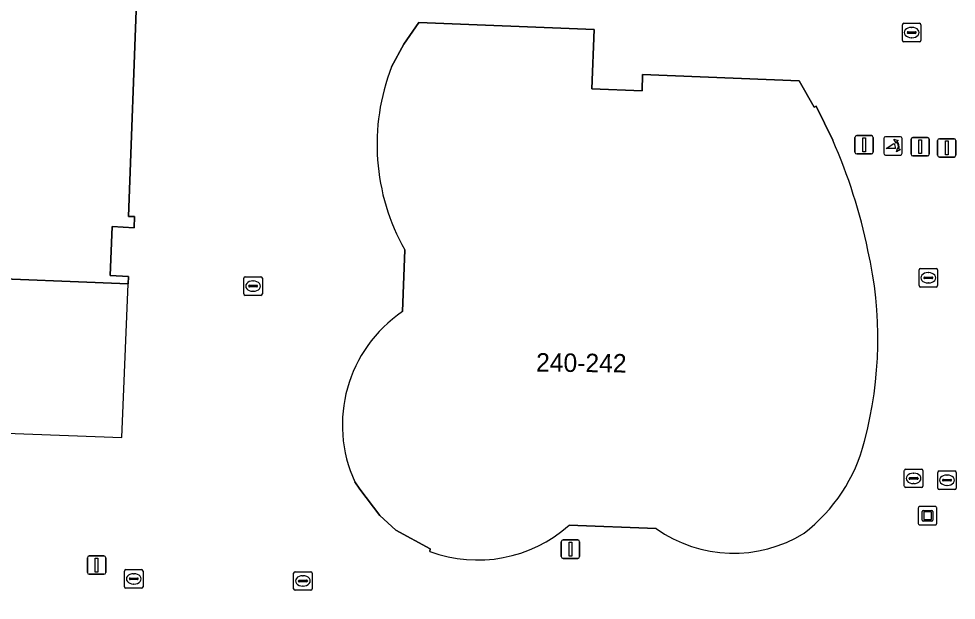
# Model space of a CAD drawing. Extents: x 160888 to 161385, y 386490 to 386908.
# Drawn here: x 161089.9 to 161140.7, y 386517.3 to 386548.8 of the extents above; entities that cross this region are included whole.
import ezdxf

# ---------------------------------------------------------------- set-up
doc = ezdxf.new("R2010")
doc.units = 0
for name, color, linetype in [('IMGEO_Afsluitpaal', 7, 'Continuous'), ('IMGEO_Kolk', 7, 'Continuous'), ('IMGEO_Kunstobject', 7, 'Continuous'), ('IMGEO_Lichtmast', 7, 'Continuous'), ('IMGEO_Pand', 7, 'Continuous'), ('IMGEO_Pand_nummerreeks', 7, 'Continuous'), ('IMGEO_Pand_overbouw', 7, 'Continuous'), ('IMGEO_Poller', 7, 'Continuous'), ('IMGEO_Rioolput', 7, 'Continuous'), ('IMGEO_Voetgangersgebied_open', 7, 'Continuous')]:
    doc.layers.add(name, color=color, linetype=linetype)

msp = doc.modelspace()

# ---------------------------------------------------------------- linework, layer by layer
at = {"layer": 'IMGEO_Afsluitpaal'}
for p, q in [((161135.291, 386542.505), (161136.081, 386542.505)), ((161136.081, 386542.505), (161135.291, 386542.505)), ((161135.191, 386541.605), (161135.191, 386542.405)), ((161135.191, 386542.405), (161135.191, 386541.605)), ((161136.181, 386542.405), (161136.181, 386541.605)), ((161136.181, 386541.605), (161136.181, 386542.405)), ((161138.234, 386541.499), (161138.234, 386542.299)), ((161138.234, 386542.299), (161138.234, 386541.499)), ((161138.334, 386542.399), (161139.124, 386542.399)), ((161139.124, 386542.399), (161138.334, 386542.399)), ((161139.224, 386542.299), (161139.224, 386541.499)), ((161139.224, 386541.499), (161139.224, 386542.299)), ((161139.674, 386541.434), (161139.674, 386542.234)), ((161139.674, 386542.234), (161139.674, 386541.434)), ((161139.774, 386542.334), (161140.564, 386542.334)), ((161140.564, 386542.334), (161139.774, 386542.334)), ((161140.664, 386542.234), (161140.664, 386541.434)), ((161140.664, 386541.434), (161140.664, 386542.234)), ((161136.081, 386541.505), (161135.291, 386541.505)), ((161135.291, 386541.505), (161136.081, 386541.505)), ((161139.124, 386541.399), (161138.334, 386541.399)), ((161138.334, 386541.399), (161139.124, 386541.399)), ((161140.564, 386541.334), (161139.774, 386541.334)), ((161139.774, 386541.334), (161140.564, 386541.334))]:
    msp.add_line(p, q, dxfattribs=at)
for points in [[(161135.611, 386542.38), (161135.761, 386542.38), (161135.761, 386541.63), (161135.611, 386541.63), (161135.611, 386542.38)], [(161138.654, 386542.274), (161138.804, 386542.274), (161138.804, 386541.524), (161138.654, 386541.524), (161138.654, 386542.274)], [(161140.094, 386542.209), (161140.244, 386542.209), (161140.244, 386541.459), (161140.094, 386541.459), (161140.094, 386542.209)]]:
    msp.add_lwpolyline(points, dxfattribs=at)
for centre, start, end in [((161135.291, 386542.405), 90, 180), ((161135.291, 386542.405), 90, 180), ((161136.081, 386542.405), 0, 90), ((161136.081, 386542.405), 360, 90), ((161138.334, 386542.299), 90, 180), ((161138.334, 386542.299), 90, 180), ((161139.124, 386542.299), 0, 90), ((161139.124, 386542.299), 360, 90), ((161139.774, 386542.234), 90, 180), ((161139.774, 386542.234), 90, 180), ((161140.564, 386542.234), 0, 90), ((161140.564, 386542.234), 360, 90), ((161135.291, 386541.605), 180, 270), ((161135.291, 386541.605), 180, 270), ((161136.081, 386541.605), 270, 0), ((161136.081, 386541.605), 270, 0), ((161138.334, 386541.499), 180, 270), ((161138.334, 386541.499), 180, 270), ((161139.124, 386541.499), 270, 0), ((161139.124, 386541.499), 270, 0), ((161139.774, 386541.434), 180, 270), ((161139.774, 386541.434), 180, 270), ((161140.564, 386541.434), 270, 0), ((161140.564, 386541.434), 270, 0)]:
    msp.add_arc(centre, 0.1, start, end, dxfattribs=at)
at = {"layer": 'IMGEO_Kolk'}
for p, q in [((161102.133, 386534.838), (161102.985, 386534.838)), ((161138.668, 386534.363), (161138.668, 386535.215)), ((161138.743, 386535.289), (161139.595, 386535.289)), ((161139.156, 386535.069), (161139.181, 386535.069)), ((161139.669, 386535.215), (161139.669, 386534.363)), ((161102.058, 386533.912), (161102.058, 386534.764)), ((161102.317, 386534.332), (161102.317, 386534.344)), ((161102.36, 386534.381), (161102.758, 386534.381)), ((161102.546, 386534.618), (161102.571, 386534.618)), ((161102.801, 386534.344), (161102.801, 386534.332)), ((161103.059, 386534.764), (161103.059, 386533.912)), ((161138.927, 386534.783), (161138.927, 386534.795)), ((161139.365, 386534.746), (161138.967, 386534.746)), ((161138.97, 386534.832), (161139.368, 386534.832)), ((161139.179, 386534.509), (161139.154, 386534.509)), ((161139.411, 386534.795), (161139.411, 386534.783)), ((161102.985, 386533.838), (161102.133, 386533.838)), ((161102.755, 386534.295), (161102.357, 386534.295)), ((161102.569, 386534.058), (161102.544, 386534.058)), ((161139.595, 386534.289), (161138.743, 386534.289)), ((161139.683, 386523.387), (161139.683, 386524.239)), ((161139.758, 386524.313), (161140.61, 386524.313)), ((161140.684, 386524.239), (161140.684, 386523.387)), ((161139.942, 386523.807), (161139.942, 386523.819)), ((161140.38, 386523.77), (161139.982, 386523.77)), ((161139.985, 386523.856), (161140.383, 386523.856)), ((161140.171, 386524.093), (161140.196, 386524.093)), ((161140.426, 386523.819), (161140.426, 386523.807)), ((161140.61, 386523.313), (161139.758, 386523.313)), ((161140.194, 386523.533), (161140.169, 386523.533)), ((161095.587, 386518.036), (161095.587, 386518.888)), ((161095.662, 386518.962), (161096.514, 386518.962)), ((161096.075, 386518.742), (161096.1, 386518.742)), ((161096.588, 386518.888), (161096.588, 386518.036)), ((161104.756, 386517.922), (161104.756, 386518.774)), ((161104.831, 386518.848), (161105.683, 386518.848)), ((161105.244, 386518.628), (161105.269, 386518.628)), ((161105.757, 386518.774), (161105.757, 386517.922)), ((161095.846, 386518.456), (161095.846, 386518.468)), ((161096.284, 386518.419), (161095.886, 386518.419)), ((161095.889, 386518.505), (161096.287, 386518.505)), ((161096.098, 386518.182), (161096.073, 386518.182)), ((161096.33, 386518.468), (161096.33, 386518.456)), ((161105.015, 386518.342), (161105.015, 386518.354)), ((161105.453, 386518.305), (161105.055, 386518.305)), ((161105.058, 386518.391), (161105.456, 386518.391)), ((161105.267, 386518.068), (161105.242, 386518.068)), ((161105.499, 386518.354), (161105.499, 386518.342)), ((161096.514, 386517.962), (161095.662, 386517.962)), ((161105.683, 386517.848), (161104.831, 386517.848))]:
    msp.add_line(p, q, dxfattribs=at)
for points in [[(161102.133, 386534.838), (161102.985, 386534.838)], [(161138.668, 386534.363), (161138.668, 386535.215)], [(161138.743, 386535.289), (161139.595, 386535.289)], [(161139.669, 386535.215), (161139.669, 386534.363)], [(161102.058, 386533.912), (161102.058, 386534.764)], [(161103.059, 386534.764), (161103.059, 386533.912)], [(161102.985, 386533.838), (161102.133, 386533.838)], [(161139.595, 386534.289), (161138.743, 386534.289)], [(161139.683, 386523.387), (161139.683, 386524.239)], [(161139.758, 386524.313), (161140.61, 386524.313)], [(161140.684, 386524.239), (161140.684, 386523.387)], [(161140.61, 386523.313), (161139.758, 386523.313)], [(161095.587, 386518.036), (161095.587, 386518.888)], [(161095.662, 386518.962), (161096.514, 386518.962)], [(161096.588, 386518.888), (161096.588, 386518.036)], [(161104.756, 386517.922), (161104.756, 386518.774)], [(161104.831, 386518.848), (161105.683, 386518.848)], [(161105.757, 386518.774), (161105.757, 386517.922)], [(161096.514, 386517.962), (161095.662, 386517.962)], [(161105.683, 386517.848), (161104.831, 386517.848)]]:
    msp.add_lwpolyline(points, dxfattribs=at)
for centre, radius, start, end in [((161102.135, 386534.762), 0.0765, 91.552, 178.448), ((161102.135, 386534.762), 0.0765, 91.552, 178.448), ((161102.983, 386534.762), 0.0765, 1.552, 88.448), ((161102.983, 386534.762), 0.0765, 1.552, 88.448), ((161138.745, 386535.213), 0.0765, 91.552, 178.448), ((161138.745, 386535.213), 0.0765, 91.552, 178.448), ((161139.593, 386535.213), 0.0765, 1.552, 88.448), ((161139.593, 386535.213), 0.0765, 1.552, 88.448), ((161102.357, 386534.341), 0.0403, 85.8775, 175.7526), ((161102.354, 386534.331), 0.0366, 178.938, 274.7102), ((161102.758, 386534.338), 0.043, 264.8664, 352.4533), ((161102.762, 386534.343), 0.0386, 1.7309, 96.639), ((161138.745, 386534.365), 0.0765, 181.552, 268.448), ((161138.745, 386534.365), 0.0765, 181.552, 268.448), ((161138.967, 386534.792), 0.0403, 85.8775, 175.7526), ((161138.964, 386534.782), 0.0366, 178.938, 274.7102), ((161139.368, 386534.789), 0.043, 264.8664, 352.4533), ((161139.372, 386534.794), 0.0386, 1.7309, 96.639), ((161139.593, 386534.365), 0.0765, 271.552, 358.448), ((161139.593, 386534.365), 0.0765, 271.552, 358.448), ((161102.135, 386533.914), 0.0765, 181.552, 268.448), ((161102.135, 386533.914), 0.0765, 181.552, 268.448), ((161102.983, 386533.914), 0.0765, 271.552, 358.448), ((161102.983, 386533.914), 0.0765, 271.552, 358.448), ((161139.76, 386524.237), 0.0765, 91.552, 178.448), ((161139.76, 386524.237), 0.0765, 91.552, 178.448), ((161140.608, 386524.237), 0.0765, 1.552, 88.448), ((161140.608, 386524.237), 0.0765, 1.552, 88.448), ((161139.982, 386523.816), 0.0403, 85.8775, 175.7526), ((161139.979, 386523.806), 0.0366, 178.938, 274.7102), ((161140.383, 386523.813), 0.043, 264.8664, 352.4533), ((161140.387, 386523.818), 0.0386, 1.7309, 96.639), ((161139.76, 386523.389), 0.0765, 181.552, 268.448), ((161139.76, 386523.389), 0.0765, 181.552, 268.448), ((161140.608, 386523.389), 0.0765, 271.552, 358.448), ((161140.608, 386523.389), 0.0765, 271.552, 358.448), ((161095.664, 386518.886), 0.0765, 91.552, 178.448), ((161095.664, 386518.886), 0.0765, 91.552, 178.448), ((161096.512, 386518.886), 0.0765, 1.552, 88.448), ((161096.512, 386518.886), 0.0765, 1.552, 88.448), ((161104.833, 386518.772), 0.0765, 91.552, 178.448), ((161104.833, 386518.772), 0.0765, 91.552, 178.448), ((161105.681, 386518.772), 0.0765, 1.552, 88.448), ((161105.681, 386518.772), 0.0765, 1.552, 88.448), ((161095.886, 386518.465), 0.0403, 85.8775, 175.7526), ((161095.883, 386518.455), 0.0366, 178.938, 274.7102), ((161096.287, 386518.462), 0.043, 264.8664, 352.4533), ((161096.291, 386518.467), 0.0386, 1.7309, 96.639), ((161105.055, 386518.351), 0.0403, 85.8775, 175.7526), ((161105.052, 386518.341), 0.0366, 178.938, 274.7102), ((161105.456, 386518.348), 0.043, 264.8664, 352.4533), ((161105.46, 386518.353), 0.0386, 1.7309, 96.639), ((161095.664, 386518.038), 0.0765, 181.552, 268.448), ((161095.664, 386518.038), 0.0765, 181.552, 268.448), ((161096.512, 386518.038), 0.0765, 271.552, 358.448), ((161096.512, 386518.038), 0.0765, 271.552, 358.448), ((161104.833, 386517.924), 0.0765, 181.552, 268.448), ((161104.833, 386517.924), 0.0765, 181.552, 268.448), ((161105.681, 386517.924), 0.0765, 271.552, 358.448), ((161105.681, 386517.924), 0.0765, 271.552, 358.448)]:
    msp.add_arc(centre, radius, start, end, dxfattribs=at)
for centre, major_axis, ratio, start_param, end_param in [((161139.155, 386534.789), (-0.387, 0.002), 0.722429, 4.712389, 7.853982), ((161139.18, 386534.789), (-0.39, 0.002), 0.717154, 1.570796, 4.712389), ((161102.545, 386534.338), (-0.387, 0.002), 0.722429, 4.712389, 7.853982), ((161102.57, 386534.338), (-0.39, 0.002), 0.717154, 1.570796, 4.712389), ((161140.17, 386523.813), (-0.387, 0.002), 0.722429, 4.712389, 7.853982), ((161140.195, 386523.813), (-0.39, 0.002), 0.717154, 1.570796, 4.712389), ((161096.074, 386518.462), (-0.387, 0.002), 0.722429, 4.712389, 7.853982), ((161096.099, 386518.462), (-0.39, 0.002), 0.717154, 1.570796, 4.712389), ((161105.243, 386518.348), (-0.387, 0.002), 0.722429, 4.712389, 7.853982), ((161105.268, 386518.348), (-0.39, 0.002), 0.717154, 1.570796, 4.712389)]:
    msp.add_ellipse(centre, major_axis=major_axis, ratio=ratio, start_param=start_param, end_param=end_param, dxfattribs=at)
at = {"layer": 'IMGEO_Kunstobject'}
for p, q in [((161138.626, 386522.301), (161138.626, 386521.46)), ((161138.626, 386522.301), (161138.626, 386521.46)), ((161139.542, 386522.385), (161138.701, 386522.385)), ((161139.542, 386522.385), (161138.701, 386522.385)), ((161138.89, 386522.173), (161139.364, 386522.173)), ((161139.626, 386521.469), (161139.626, 386522.31)), ((161139.626, 386521.469), (161139.626, 386522.31)), ((161138.84, 386521.649), (161138.84, 386522.123)), ((161138.92, 386522.073), (161138.92, 386521.699)), ((161139.314, 386522.093), (161138.94, 386522.093)), ((161138.94, 386521.679), (161139.314, 386521.679)), ((161139.334, 386521.699), (161139.334, 386522.073)), ((161139.414, 386522.123), (161139.414, 386521.649)), ((161138.71, 386521.385), (161139.551, 386521.385)), ((161138.71, 386521.385), (161139.551, 386521.385)), ((161139.364, 386521.599), (161138.89, 386521.599))]:
    msp.add_line(p, q, dxfattribs=at)
for centre, radius, start, end in [((161138.704, 386522.307), 0.0779, 92.4484, 184.2845), ((161138.704, 386522.307), 0.0779, 92.4484, 184.2845), ((161138.89, 386522.123), 0.05, 90, 180), ((161139.364, 386522.123), 0.05, 360, 90), ((161139.548, 386522.307), 0.0779, 2.4484, 94.2845), ((161139.548, 386522.307), 0.0779, 2.4484, 94.2845), ((161138.89, 386521.649), 0.05, 180, 270), ((161138.94, 386522.073), 0.02, 90, 180), ((161138.94, 386521.699), 0.02, 180, 270), ((161139.314, 386522.073), 0.02, 360, 90), ((161139.314, 386521.699), 0.02, 270, 0), ((161139.364, 386521.649), 0.05, 270, 0), ((161138.704, 386521.463), 0.0779, 182.4484, 274.2845), ((161138.704, 386521.463), 0.0779, 182.4484, 274.2845), ((161139.548, 386521.463), 0.0779, 272.4484, 4.2845), ((161139.548, 386521.463), 0.0779, 272.4484, 4.2845)]:
    msp.add_arc(centre, radius, start, end, dxfattribs=at)
at = {"layer": 'IMGEO_Lichtmast'}
for p, q in [((161119.269, 386519.671), (161119.269, 386520.471)), ((161119.269, 386520.471), (161119.269, 386519.671)), ((161119.369, 386520.571), (161120.159, 386520.571)), ((161120.159, 386520.571), (161119.369, 386520.571)), ((161120.259, 386520.471), (161120.259, 386519.671)), ((161120.259, 386519.671), (161120.259, 386520.471)), ((161093.573, 386518.808), (161093.573, 386519.608)), ((161093.573, 386519.608), (161093.573, 386518.808)), ((161093.673, 386519.708), (161094.463, 386519.708)), ((161094.463, 386519.708), (161093.673, 386519.708)), ((161094.563, 386519.608), (161094.563, 386518.808)), ((161094.563, 386518.808), (161094.563, 386519.608)), ((161120.159, 386519.571), (161119.369, 386519.571)), ((161119.369, 386519.571), (161120.159, 386519.571)), ((161094.463, 386518.708), (161093.673, 386518.708)), ((161093.673, 386518.708), (161094.463, 386518.708))]:
    msp.add_line(p, q, dxfattribs=at)
for points in [[(161119.689, 386520.446), (161119.839, 386520.446), (161119.839, 386519.696), (161119.689, 386519.696), (161119.689, 386520.446)], [(161093.993, 386519.583), (161094.143, 386519.583), (161094.143, 386518.833), (161093.993, 386518.833), (161093.993, 386519.583)]]:
    msp.add_lwpolyline(points, dxfattribs=at)
for centre, start, end in [((161119.369, 386520.471), 90, 180), ((161119.369, 386520.471), 90, 180), ((161120.159, 386520.471), 0, 90), ((161120.159, 386520.471), 360, 90), ((161093.673, 386519.608), 90, 180), ((161093.673, 386519.608), 90, 180), ((161094.463, 386519.608), 0, 90), ((161094.463, 386519.608), 360, 90), ((161119.369, 386519.671), 180, 270), ((161119.369, 386519.671), 180, 270), ((161120.159, 386519.671), 270, 0), ((161120.159, 386519.671), 270, 0), ((161093.673, 386518.808), 180, 270), ((161093.673, 386518.808), 180, 270), ((161094.463, 386518.808), 270, 0), ((161094.463, 386518.808), 270, 0)]:
    msp.add_arc(centre, 0.1, start, end, dxfattribs=at)
at = {"layer": 'IMGEO_Pand'}
for points in [[(161002.953, 386513.11), (161051.083, 386511.057), (161051.206, 386511.052), (161052.017, 386528.899), (161080.022, 386527.764), (161080.132, 386529.382), (161081.504, 386529.308), (161086.537, 386529.035), (161086.775, 386534.825), (161095.779, 386534.461), (161095.797, 386534.862), (161094.798, 386534.906), (161094.918, 386537.567), (161096.112, 386537.502), (161096.134, 386538.109), (161095.807, 386538.111), (161096.256, 386550.282), (161074.659, 386551.192), (161041.832, 386552.576), (161041.925, 386554.908), (161042.136, 386560.18), (161042.986, 386581.802), (161011.368, 386583.058)], [(161133.984, 386542.246), (161133.082, 386544.09), (161132.989, 386544.045), (161132.172, 386545.476), (161123.673, 386545.824), (161123.652, 386544.924), (161120.928, 386545.042), (161121.056, 386548.259), (161111.552, 386548.634), (161110.736, 386547.454), (161110.068, 386546.223)], [(161110.787, 386536.307), (161110.654, 386532.956)], [(161108.077, 386523.72), (161108.346, 386523.332), (161109.425, 386521.897), (161110.299, 386521.096), (161112.164, 386520.096), (161112.145, 386519.949)], [(161119.688, 386521.369), (161124.412, 386521.191)]]:
    msp.add_lwpolyline(points, dxfattribs=at)
for centre, radius, start, end in [((161120.826, 386542.019), 11.551, 158.6561, 209.6383), ((161107.732, 386530.554), 28.738, 11.4916, 24.0075), ((161114.811, 386531.479), 21.623, 345.1161, 12.8256), ((161114.811, 386526.819), 7.412, 124.1093, 204.7107), ((161126.927, 386528.129), 9.053, 307.4647, 345.9122), ((161114.735, 386526.936), 7.451, 249.6615, 311.6613), ((161128.61, 386527.104), 7.252, 234.6294, 301.8291)]:
    msp.add_arc(centre, radius, start, end, dxfattribs=at)
at = {"layer": 'IMGEO_Pand_overbouw'}
msp.add_lwpolyline([(161080.022, 386527.764), (161079.988, 386526.704), (161081.426, 386526.65), (161095.446, 386526.126), (161095.779, 386534.461), (161086.775, 386534.825), (161086.537, 386529.035), (161081.504, 386529.308), (161080.132, 386529.382)], close=True, dxfattribs=at)
at = {"layer": 'IMGEO_Poller'}
for p, q in [((161136.755, 386542.347), (161136.755, 386541.54)), ((161136.755, 386542.347), (161136.755, 386541.54)), ((161137.657, 386542.442), (161136.849, 386542.442)), ((161137.657, 386542.442), (161136.849, 386542.442)), ((161137.751, 386541.54), (161137.751, 386542.347)), ((161137.751, 386541.54), (161137.751, 386542.347)), ((161136.849, 386541.445), (161137.657, 386541.445)), ((161136.849, 386541.445), (161137.657, 386541.445))]:
    msp.add_line(p, q, dxfattribs=at)
for points in [[(161137.39, 386541.798), (161136.877, 386541.798), (161137.307, 386542.073)], [(161137.434, 386542.171), (161137.422, 386542.098), (161137.297, 386542.303)], [(161137.297, 386542.303), (161137.528, 386542.237), (161137.457, 386542.205)], [(161137.45, 386541.626), (161137.516, 386541.857), (161137.546, 386541.789)], [(161137.582, 386541.762), (161137.654, 386541.751), (161137.45, 386541.626)]]:
    msp.add_lwpolyline(points, dxfattribs=at)
for centre, radius, start, end in [((161136.849, 386542.347), 0.0946, 90, 180), ((161136.849, 386542.347), 0.0946, 90, 180), ((161137.062, 386541.848), 0.332, 351.3247, 42.4854), ((161137.076, 386541.858), 0.476, 351.7527, 41.1691), ((161137.076, 386541.858), 0.516, 349.3569, 42.2912), ((161137.657, 386542.347), 0.0946, 0, 90), ((161137.657, 386542.347), 0.0946, 0, 90), ((161136.849, 386541.54), 0.0946, 180, 270), ((161136.849, 386541.54), 0.0946, 180, 270), ((161137.657, 386541.54), 0.0946, 270, 0), ((161137.657, 386541.54), 0.0946, 270, 0)]:
    msp.add_arc(centre, radius, start, end, dxfattribs=at)
at = {"layer": 'IMGEO_Rioolput'}
for p, q in [((161137.844, 386548.59), (161138.696, 386548.59)), ((161137.769, 386547.664), (161137.769, 386548.516)), ((161138.028, 386548.084), (161138.028, 386548.096)), ((161138.071, 386548.133), (161138.469, 386548.133)), ((161138.257, 386548.37), (161138.282, 386548.37)), ((161138.512, 386548.096), (161138.512, 386548.084)), ((161138.77, 386548.516), (161138.77, 386547.664)), ((161138.696, 386547.59), (161137.844, 386547.59)), ((161138.466, 386548.047), (161138.068, 386548.047)), ((161138.28, 386547.81), (161138.255, 386547.81)), ((161137.869, 386523.484), (161137.869, 386524.336)), ((161137.944, 386524.41), (161138.796, 386524.41)), ((161138.357, 386524.19), (161138.382, 386524.19)), ((161138.87, 386524.336), (161138.87, 386523.484)), ((161138.128, 386523.904), (161138.128, 386523.916)), ((161138.566, 386523.867), (161138.168, 386523.867)), ((161138.171, 386523.953), (161138.569, 386523.953)), ((161138.612, 386523.916), (161138.612, 386523.904)), ((161138.796, 386523.41), (161137.944, 386523.41)), ((161138.38, 386523.63), (161138.355, 386523.63))]:
    msp.add_line(p, q, dxfattribs=at)
for points in [[(161137.844, 386548.59), (161138.696, 386548.59)], [(161137.769, 386547.664), (161137.769, 386548.516)], [(161138.77, 386548.516), (161138.77, 386547.664)], [(161138.696, 386547.59), (161137.844, 386547.59)], [(161137.869, 386523.484), (161137.869, 386524.336)], [(161137.944, 386524.41), (161138.796, 386524.41)], [(161138.87, 386524.336), (161138.87, 386523.484)], [(161138.796, 386523.41), (161137.944, 386523.41)]]:
    msp.add_lwpolyline(points, dxfattribs=at)
for centre, radius, start, end in [((161137.846, 386548.514), 0.0765, 91.552, 178.448), ((161137.846, 386548.514), 0.0765, 91.552, 178.448), ((161138.694, 386548.514), 0.0765, 1.552, 88.448), ((161138.694, 386548.514), 0.0765, 1.552, 88.448), ((161138.068, 386548.093), 0.0403, 85.8775, 175.7526), ((161138.065, 386548.083), 0.0366, 178.938, 274.7102), ((161138.469, 386548.09), 0.043, 264.8664, 352.4533), ((161138.473, 386548.095), 0.0386, 1.7309, 96.639), ((161137.846, 386547.666), 0.0765, 181.552, 268.448), ((161137.846, 386547.666), 0.0765, 181.552, 268.448), ((161138.694, 386547.666), 0.0765, 271.552, 358.448), ((161138.694, 386547.666), 0.0765, 271.552, 358.448), ((161137.946, 386524.334), 0.0765, 91.552, 178.448), ((161137.946, 386524.334), 0.0765, 91.552, 178.448), ((161138.794, 386524.334), 0.0765, 1.552, 88.448), ((161138.794, 386524.334), 0.0765, 1.552, 88.448), ((161138.168, 386523.913), 0.0403, 85.8775, 175.7526), ((161138.165, 386523.903), 0.0366, 178.938, 274.7102), ((161138.569, 386523.91), 0.043, 264.8664, 352.4533), ((161138.573, 386523.915), 0.0386, 1.7309, 96.639), ((161137.946, 386523.486), 0.0765, 181.552, 268.448), ((161137.946, 386523.486), 0.0765, 181.552, 268.448), ((161138.794, 386523.486), 0.0765, 271.552, 358.448), ((161138.794, 386523.486), 0.0765, 271.552, 358.448)]:
    msp.add_arc(centre, radius, start, end, dxfattribs=at)
for centre, major_axis, ratio, start_param, end_param in [((161138.256, 386548.09), (-0.387, 0.002), 0.722429, 4.712389, 7.853982), ((161138.281, 386548.09), (-0.39, 0.002), 0.717154, 1.570796, 4.712389), ((161138.356, 386523.91), (-0.387, 0.002), 0.722429, 4.712389, 7.853982), ((161138.381, 386523.91), (-0.39, 0.002), 0.717154, 1.570796, 4.712389)]:
    msp.add_ellipse(centre, major_axis=major_axis, ratio=ratio, start_param=start_param, end_param=end_param, dxfattribs=at)
at = {"layer": 'IMGEO_Voetgangersgebied_open'}
for points in [[(161042.986, 386581.802), (161042.136, 386560.18), (161041.925, 386554.908), (161041.832, 386552.576), (161074.659, 386551.192), (161096.256, 386550.282), (161095.807, 386538.111), (161096.134, 386538.109), (161096.112, 386537.502), (161094.918, 386537.567), (161094.798, 386534.906), (161095.797, 386534.862), (161095.779, 386534.461), (161086.775, 386534.825), (161086.537, 386529.035), (161081.504, 386529.308), (161080.132, 386529.382), (161080.022, 386527.764), (161052.017, 386528.899), (161051.206, 386511.052), (161051.083, 386511.057), (161051.677, 386507.711), (161054.692, 386507.633), (161095.632, 386509.131)], [(161110.068, 386546.223), (161110.736, 386547.454), (161111.552, 386548.634), (161121.056, 386548.259), (161120.928, 386545.042), (161123.652, 386544.924), (161123.673, 386545.824), (161132.172, 386545.476), (161132.989, 386544.045), (161133.082, 386544.09), (161133.984, 386542.246)], [(161110.654, 386532.956), (161110.787, 386536.307)], [(161112.145, 386519.949), (161112.164, 386520.096), (161110.299, 386521.096), (161109.425, 386521.897), (161108.346, 386523.332), (161108.077, 386523.72)], [(161124.412, 386521.191), (161119.688, 386521.369)]]:
    msp.add_lwpolyline(points, dxfattribs=at)
for centre, radius, start, end in [((161120.826, 386542.019), 11.551, 158.6561, 209.6383), ((161107.732, 386530.554), 28.738, 11.4916, 24.0075), ((161114.811, 386531.479), 21.623, 345.1161, 12.8256), ((161114.811, 386526.819), 7.412, 124.1093, 204.7107), ((161126.927, 386528.129), 9.053, 307.4647, 345.9122), ((161114.735, 386526.936), 7.451, 249.6615, 311.6613), ((161128.61, 386527.104), 7.252, 234.6294, 301.8291)]:
    msp.add_arc(centre, radius, start, end, dxfattribs=at)

# ---------------------------------------------------------------- texts
at = {"layer": 'IMGEO_Pand_nummerreeks'}
msp.add_text('240-242', height=1, rotation=359.3504, dxfattribs=at).set_placement((161117.896, 386529.706))

doc.saveas('drawing.dxf')
